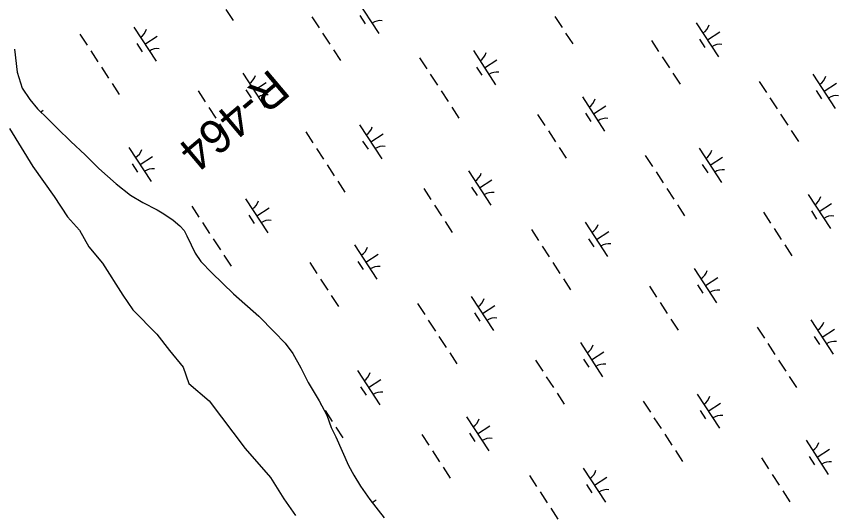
# Model space of a CAD drawing. Extents: x 3953924 to 3974542, y 193747 to 216192.
# Drawn here: x 3968214 to 3969220, y 199454 to 200062 of the extents above; entities that cross this region are included whole.
import ezdxf

# ---------------------------------------------------------------- set-up
doc = ezdxf.new("R2010")
doc.units = 0
for name, color, linetype in [('V-RIVR-EDGE', 7, 'Continuous'), ('V-RIVR-RANG-IDEN', 7, 'Continuous'), ('V-WETL-SWMP', 7, 'Continuous')]:
    doc.layers.add(name, color=color, linetype=linetype)

msp = doc.modelspace()

# ---------------------------------------------------------------- linework, layer by layer
at = {"layer": 'V-RIVR-EDGE'}
msp.add_lwpolyline([(3968205.4, 199924.4), (3968233.9, 199878.1), (3968260, 199841.3), (3968276.6, 199816.4), (3968290.9, 199799.8), (3968302.7, 199779.6), (3968319.4, 199759.4), (3968344.3, 199720.2), (3968356.2, 199702.4), (3968385.8, 199672.7), (3968401.3, 199652.5), (3968417.9, 199632.4), (3968425, 199612.2), (3968450, 199590.8), (3968493.9, 199532.6), (3968524.7, 199497), (3968541.4, 199470.9), (3968555.6, 199450.7)], dxfattribs=at)
at = {"layer": 'V-WETL-SWMP'}
for p, q in [((3968630.3, 200082.9), (3968657.6, 200041)), ((3968470.4, 200070.3), (3968479.1, 200056.9)), ((3968575.6, 200061.2), (3968584.3, 200047.8)), ((3968634.2, 200062.8), (3968640.8, 200052.7)), ((3968873, 200061.5), (3968881.7, 200048.1)), ((3968357.5, 200048.8), (3968384.8, 200006.9)), ((3969046.1, 200054.1), (3969073.3, 200012.2)), ((3968291.7, 200039.9), (3968300.4, 200026.5)), ((3968371.2, 200027.8), (3968386.2, 200037.7)), ((3968588.7, 200041.1), (3968597.4, 200027.7)), ((3968886.1, 200041.4), (3968894.8, 200028)), ((3969059.7, 200033.1), (3969074.8, 200043)), ((3968361.4, 200028.7), (3968368, 200018.6)), ((3968991.3, 200032.4), (3969000, 200019)), ((3969050, 200034), (3969056.5, 200023.9)), ((3968211.6, 200021.6), (3968214.9, 199993.7)), ((3968304.8, 200019.7), (3968313.5, 200006.3)), ((3968601.8, 200021), (3968610.5, 200007.6)), ((3968773.2, 200020), (3968800.5, 199978.1)), ((3968707.4, 200011), (3968716.1, 199997.6)), ((3968786.9, 199999), (3968802, 200008.8)), ((3969004.4, 200012.3), (3969013.1, 199998.9)), ((3968317.9, 199999.6), (3968326.6, 199986.2)), ((3968777.1, 199999.8), (3968783.7, 199989.8)), ((3968214.9, 199993.7), (3968221, 199974.1)), ((3968490.9, 199992.2), (3968518.2, 199950.3)), ((3968720.5, 199990.9), (3968729.2, 199977.5)), ((3969017.5, 199992.2), (3969026.2, 199978.8)), ((3969188.9, 199991.1), (3969216.2, 199949.2)), ((3968221, 199974.1), (3968230.3, 199960.2)), ((3968331, 199979.5), (3968339.7, 199966.1)), ((3968504.6, 199971.2), (3968519.7, 199981)), ((3969123.1, 199982.2), (3969131.9, 199968.8)), ((3969202.6, 199970.2), (3969217.7, 199980)), ((3968436.2, 199970.5), (3968444.9, 199957.1)), ((3968494.8, 199972), (3968501.4, 199962)), ((3968733.6, 199970.8), (3968742.3, 199957.4)), ((3969192.8, 199971), (3969199.4, 199960.9)), ((3968230.3, 199960.2), (3968239.6, 199948.6)), ((3968906.7, 199963.3), (3968933.9, 199921.4)), ((3969136.2, 199962.1), (3969144.9, 199948.7)), ((3968239.6, 199948.6), (3968252.3, 199936.2)), ((3968243.5, 199944.7), (3968246.8, 199946.9)), ((3968449.3, 199950.4), (3968458, 199937)), ((3968746.7, 199950.7), (3968755.4, 199937.3)), ((3968920.3, 199942.4), (3968935.4, 199952.2)), ((3968252.3, 199936.2), (3968263.9, 199924.9)), ((3968851.9, 199941.7), (3968860.6, 199928.3)), ((3968910.6, 199943.2), (3968917.1, 199933.2)), ((3969149.3, 199942), (3969158, 199928.6)), ((3968263.9, 199924.9), (3968280.3, 199908.5)), ((3968462.4, 199930.3), (3968471.1, 199916.9)), ((3968633.8, 199929.2), (3968661.1, 199887.3)), ((3968568, 199920.3), (3968576.7, 199906.9)), ((3968647.5, 199908.3), (3968662.6, 199918.1)), ((3968865, 199921.6), (3968873.7, 199908.1)), ((3969162.4, 199921.9), (3969171.1, 199908.4)), ((3968280.3, 199908.5), (3968297.9, 199892.2)), ((3968637.7, 199909.1), (3968644.3, 199899)), ((3968351.5, 199901.4), (3968378.8, 199859.5)), ((3968581.1, 199900.2), (3968589.8, 199886.8)), ((3968878.1, 199901.4), (3968886.8, 199888)), ((3969049.5, 199900.4), (3969076.8, 199858.5)), ((3968297.9, 199892.2), (3968314.8, 199875.5)), ((3968365.2, 199880.5), (3968380.3, 199890.3)), ((3968983.7, 199891.5), (3968992.5, 199878)), ((3969063.2, 199879.4), (3969078.3, 199889.3)), ((3968314.8, 199875.5), (3968336.1, 199856.8)), ((3968355.4, 199881.3), (3968362, 199871.2)), ((3968594.2, 199880.1), (3968602.9, 199866.6)), ((3969053.4, 199880.3), (3969060, 199870.2)), ((3968767.2, 199872.6), (3968794.5, 199830.7)), ((3968996.8, 199871.3), (3969005.5, 199857.9)), ((3968336.1, 199856.8), (3968353.4, 199842.7)), ((3968607.3, 199859.9), (3968616, 199846.5)), ((3968780.9, 199851.7), (3968796, 199861.5)), ((3968712.5, 199850.9), (3968721.2, 199837.5)), ((3968771.1, 199852.5), (3968777.7, 199842.4)), ((3969009.9, 199851.2), (3969018.6, 199837.8)), ((3969183, 199843.8), (3969210.2, 199801.9)), ((3968353.4, 199842.7), (3968368.8, 199834)), ((3968368.8, 199834), (3968386.2, 199824.9)), ((3968494.4, 199838.5), (3968521.7, 199796.6)), ((3968386.2, 199824.9), (3968394.5, 199820.2)), ((3968428.6, 199829.5), (3968437.3, 199816.1)), ((3968508.1, 199817.5), (3968523.1, 199827.3)), ((3968725.6, 199830.8), (3968734.3, 199817.4)), ((3969023, 199831.1), (3969031.7, 199817.7)), ((3969186.9, 199823.6), (3969193.4, 199813.6)), ((3969196.6, 199822.8), (3969211.7, 199832.6)), ((3968394.5, 199820.2), (3968405.8, 199812.3)), ((3968498.3, 199818.3), (3968504.9, 199808.3)), ((3969128.2, 199822.1), (3969136.9, 199808.7)), ((3968405.8, 199812.3), (3968414, 199805.3)), ((3968414, 199805.3), (3968419.3, 199799.5)), ((3968441.7, 199809.4), (3968450.4, 199796)), ((3968738.7, 199810.7), (3968747.4, 199797.3)), ((3968910.1, 199809.6), (3968937.4, 199767.7)), ((3968419.3, 199799.5), (3968422.6, 199793)), ((3968422.6, 199793), (3968427.7, 199782.2)), ((3968844.3, 199800.7), (3968853, 199787.3)), ((3968923.8, 199788.7), (3968938.9, 199798.5)), ((3969141.3, 199802), (3969150, 199788.6)), ((3968454.8, 199789.3), (3968463.5, 199775.9)), ((3968914, 199789.5), (3968920.6, 199779.5)), ((3968427.7, 199782.2), (3968432.8, 199771.8)), ((3968627.8, 199781.9), (3968655.1, 199740)), ((3968857.4, 199780.6), (3968866.1, 199767.2)), ((3969154.4, 199781.9), (3969163.1, 199768.5)), ((3968432.8, 199771.8), (3968439.5, 199761.8)), ((3968467.9, 199769.2), (3968476.6, 199755.8)), ((3968641.5, 199760.9), (3968656.6, 199770.7)), ((3968439.5, 199761.8), (3968452.9, 199747.8)), ((3968573.1, 199760.2), (3968581.8, 199746.8)), ((3968631.7, 199761.7), (3968638.3, 199751.7)), ((3968870.5, 199760.5), (3968879.2, 199747.1)), ((3969043.6, 199753), (3969070.8, 199711.1)), ((3968452.9, 199747.8), (3968479.5, 199722.1)), ((3968586.2, 199740.1), (3968594.9, 199726.7)), ((3968883.6, 199740.4), (3968892.3, 199727)), ((3969047.5, 199732.9), (3969054, 199722.8)), ((3969057.2, 199732.1), (3969072.3, 199741.9)), ((3968988.8, 199731.3), (3968997.5, 199717.9)), ((3968479.5, 199722.1), (3968510.6, 199694.8)), ((3968599.3, 199720), (3968608, 199706.5)), ((3968770.7, 199718.9), (3968798, 199677)), ((3968704.9, 199710), (3968713.6, 199696.6)), ((3968784.4, 199697.9), (3968799.5, 199707.8)), ((3969001.9, 199711.2), (3969010.6, 199697.8)), ((3968510.6, 199694.8), (3968529.2, 199675.3)), ((3968774.6, 199698.8), (3968781.2, 199688.7)), ((3968718, 199689.9), (3968726.7, 199676.4)), ((3969015, 199691.1), (3969023.7, 199677.7)), ((3969186.4, 199690.1), (3969213.7, 199648.2)), ((3968529.2, 199675.3), (3968543, 199661.5)), ((3969120.6, 199681.1), (3969129.4, 199667.7)), ((3969200.1, 199669.1), (3969215.2, 199678.9)), ((3968731.1, 199669.7), (3968739.8, 199656.3)), ((3968904.2, 199662.3), (3968931.4, 199620.4)), ((3969190.3, 199669.9), (3969196.9, 199659.9)), ((3968543, 199661.5), (3968552.1, 199648.8)), ((3969133.7, 199661), (3969142.4, 199647.6)), ((3968552.1, 199648.8), (3968561.9, 199631.4)), ((3968744.2, 199649.6), (3968752.9, 199636.2)), ((3968908.1, 199642.1), (3968914.6, 199632.1)), ((3968917.8, 199641.3), (3968932.9, 199651.1)), ((3968849.4, 199640.6), (3968858.1, 199627.2)), ((3969146.8, 199640.9), (3969155.5, 199627.5)), ((3968561.9, 199631.4), (3968571.1, 199613.5)), ((3968631.3, 199628.2), (3968658.6, 199586.2)), ((3968571.1, 199613.5), (3968584.5, 199590.9)), ((3968645, 199607.2), (3968660.1, 199617)), ((3968862.5, 199620.5), (3968871.2, 199607.1)), ((3969159.9, 199620.8), (3969168.6, 199607.4)), ((3968635.2, 199608), (3968641.8, 199598)), ((3968875.6, 199600.4), (3968884.3, 199587)), ((3969047, 199599.3), (3969074.3, 199557.4)), ((3968584.5, 199590.9), (3968593.7, 199573.5)), ((3968586.7, 199586.6), (3968587.3, 199585.7)), ((3968981.2, 199590.4), (3968990, 199577)), ((3969060.7, 199578.4), (3969075.8, 199588.2)), ((3968591.7, 199579), (3968600.4, 199565.6)), ((3968593.7, 199573.5), (3968599.3, 199558.4)), ((3968764.7, 199571.5), (3968792, 199529.6)), ((3969050.9, 199579.2), (3969057.5, 199569.1)), ((3968994.3, 199570.3), (3969003, 199556.9)), ((3968599.3, 199558.4), (3968604.8, 199546.8)), ((3968604.8, 199558.9), (3968613.5, 199545.5)), ((3968768.6, 199551.4), (3968775.2, 199541.3)), ((3968778.4, 199550.6), (3968793.5, 199560.4)), ((3968604.8, 199546.8), (3968620.2, 199511.9)), ((3968710, 199549.9), (3968718.7, 199536.5)), ((3969007.4, 199550.2), (3969016.1, 199536.8)), ((3969180.5, 199542.7), (3969207.7, 199500.8)), ((3969194.1, 199521.8), (3969209.2, 199531.6)), ((3968723.1, 199529.7), (3968731.8, 199516.3)), ((3969020.5, 199530), (3969029.2, 199516.6)), ((3969184.4, 199522.6), (3969190.9, 199512.5)), ((3968620.2, 199511.9), (3968627, 199499.8)), ((3969125.7, 199521), (3969134.4, 199507.6)), ((3968736.2, 199509.6), (3968744.9, 199496.2)), ((3968907.6, 199508.6), (3968934.9, 199466.7)), ((3968627, 199499.8), (3968634.9, 199486.4)), ((3968841.8, 199499.6), (3968850.5, 199486.2)), ((3968921.3, 199487.6), (3968936.4, 199497.4)), ((3969138.8, 199500.9), (3969147.5, 199487.5)), ((3968634.9, 199486.4), (3968646.4, 199470.3)), ((3968911.5, 199488.4), (3968918.1, 199478.4)), ((3968854.9, 199479.5), (3968863.6, 199466.1)), ((3969151.9, 199480.8), (3969160.6, 199467.4)), ((3968646.4, 199470.3), (3968663.9, 199447.8)), ((3968649.3, 199466.6), (3968654.1, 199469.7)), ((3968868, 199459.4), (3968876.7, 199446))]:
    msp.add_line(p, q, dxfattribs=at)
for centre, start, end in [((3968659.2, 200039), 82.2901, 123.8337), ((3968356.3, 200051.1), 302.2901, 343.8338), ((3969044.8, 200056.4), 302.2901, 343.8338), ((3969075, 200010.1), 82.2901, 123.8337), ((3968386.4, 200004.8), 82.2901, 123.8337), ((3968772, 200022.3), 302.2901, 343.8338), ((3968489.7, 199994.5), 302.2901, 343.8338), ((3968802.1, 199976), 82.2901, 123.8337), ((3969187.7, 199993.5), 302.2901, 343.8338), ((3968519.8, 199948.2), 82.2901, 123.8337), ((3969217.9, 199947.2), 82.2901, 123.8337), ((3968905.4, 199965.7), 302.2901, 343.8338), ((3968935.6, 199919.4), 82.2901, 123.8337), ((3968632.6, 199931.5), 302.2901, 343.8338), ((3968350.3, 199903.8), 302.2901, 343.8338), ((3968662.7, 199885.2), 82.2901, 123.8337), ((3969048.3, 199902.7), 302.2901, 343.8338), ((3968380.4, 199857.5), 82.2901, 123.8337), ((3969078.4, 199856.4), 82.2901, 123.8337), ((3968766, 199874.9), 302.2901, 343.8338), ((3968796.2, 199828.6), 82.2901, 123.8337), ((3968493.2, 199840.8), 302.2901, 343.8338), ((3969181.7, 199846.1), 302.2901, 343.8338), ((3969211.9, 199799.8), 82.2901, 123.8337), ((3968523.3, 199794.5), 82.2901, 123.8337), ((3968908.9, 199812), 302.2901, 343.8338), ((3968939, 199765.7), 82.2901, 123.8337), ((3968626.6, 199784.2), 302.2901, 343.8338), ((3968656.7, 199737.9), 82.2901, 123.8337), ((3969042.3, 199755.4), 302.2901, 343.8338), ((3969072.5, 199709.1), 82.2901, 123.8337), ((3968769.5, 199721.2), 302.2901, 343.8338), ((3968799.6, 199674.9), 82.2901, 123.8337), ((3969185.2, 199692.4), 302.2901, 343.8338), ((3969215.4, 199646.1), 82.2901, 123.8337), ((3968902.9, 199664.6), 302.2901, 343.8338), ((3968933.1, 199618.3), 82.2901, 123.8337), ((3968630.1, 199630.5), 302.2901, 343.8338), ((3968660.2, 199584.2), 82.2901, 123.8337), ((3969045.8, 199601.6), 302.2901, 343.8338), ((3969076, 199555.4), 82.2901, 123.8337), ((3968763.5, 199573.9), 302.2901, 343.8338), ((3968793.7, 199527.6), 82.2901, 123.8337), ((3969179.2, 199545), 302.2901, 343.8338), ((3969209.4, 199498.7), 82.2901, 123.8337), ((3968906.4, 199510.9), 302.2901, 343.8338), ((3968936.5, 199464.6), 82.2901, 123.8337), ((3968624.1, 199483.1), 342.8525, 343.8338)]:
    msp.add_arc(centre, 17.6, start, end, dxfattribs=at)

# ---------------------------------------------------------------- texts
at = {"layer": 'V-RIVR-RANG-IDEN'}
msp.add_text('R-464  ', height=41.5, rotation=220.1407, dxfattribs=at).set_placement((3968524.7, 199998.7))

doc.saveas('drawing.dxf')
